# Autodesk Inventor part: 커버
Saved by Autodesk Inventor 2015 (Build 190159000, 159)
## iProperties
Created: 2024-12
Part Number: 커버
Material: 일반
Document SubType Name: Modeling
Designer: 102-5
Density: 1 g/cm^3
Appearance: 기본값
Author: 102-5
Author: jhkim
Creation Date: 2024-11-28
Sending System: Autodesk Inventor 2025
Preprocessor: ST-DEVELOPER v20
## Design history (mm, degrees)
node "커버1"
node "솔리드1"
node "기준1"
